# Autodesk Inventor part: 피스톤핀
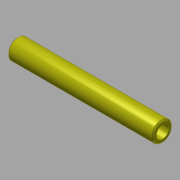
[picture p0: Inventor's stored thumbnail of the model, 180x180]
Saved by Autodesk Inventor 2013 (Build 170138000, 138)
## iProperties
Created: 2016-11
Part Number: 피스톤핀
Material: 강철, 탄소
Document SubType Name: Modeling
Designer: mduedu
Density: 7.87 g/cm^3
Mass: 13.9342 g
Surface Area: 24.1465 cm^2
Volume: 1.77055 cm^3
Author: mduedu
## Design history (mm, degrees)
sketch "스케치1"
  geometry: C1 r 2.5 at (0, 0); C2 r 4 at (0, 0); 1 further point
  constraints: 2 centre point, 2 coincident
  dimensions: "d0" = 5 diameter of C1; "d1" = 8 diameter of C2
extrude "돌출1" new body sketch "스케치1" stored distance "d2" = 58; taper "d3" = 0 deg
chamfer "모따기1" distance "d4" = 0.5; stored, may be unused: second distance "d5" = 2, angle "d6" = 45 deg
node "솔리드1"
